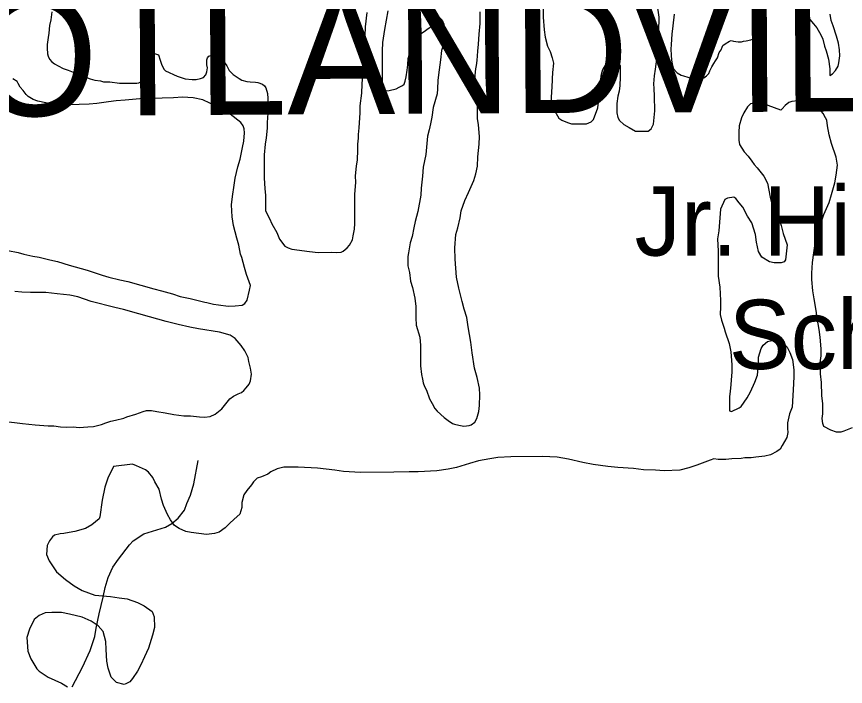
# Model space of a CAD drawing. Extents: x 3313442 to 3351311, y 721974 to 747360.
# Drawn here: x 3330734 to 3331726, y 737982 to 738784 of the extents above; entities that cross this region are included whole.
import ezdxf

# ---------------------------------------------------------------- set-up
doc = ezdxf.new("R2010")
doc.units = 0
for name, color, linetype in [('V-BLDG-IDEN', 7, 'Continuous'), ('V-SITE-VEGE', 7, 'Continuous'), ('V-TOPO-GNAM-IDEN', 7, 'Continuous'), ('V-TOPO-SHOR', 7, 'Continuous')]:
    doc.layers.add(name, color=color, linetype=linetype)

msp = doc.modelspace()

# ---------------------------------------------------------------- linework, layer by layer
at = {"layer": 'V-SITE-VEGE'}
for points in [[(3331364.25, 738793.3), (3331364.33, 738783.3), (3331365.48, 738768.15), (3331366.59, 738759.2), (3331369.43, 738748.54), (3331372.58, 738742.36), (3331375.06, 738734.8), (3331376.49, 738728.26), (3331375.54, 738716.88), (3331375.26, 738709.64), (3331374.66, 738698.61), (3331374.34, 738695.16), (3331373.73, 738685.85), (3331373.77, 738680.34), (3331376.94, 738672.09), (3331379.73, 738667.98), (3331383.22, 738662.49), (3331386.68, 738660.11), (3331393.26, 738657.06), (3331398.09, 738655.72), (3331401.88, 738655.75), (3331406.71, 738655.45), (3331416.36, 738655.53), (3331421.85, 738657.98), (3331424.58, 738660.76), (3331429.64, 738674.59), (3331431.92, 738691.49), (3331432.19, 738700.45), (3331432.83, 738706.32), (3331434.14, 738714.94), (3331435.82, 738720.47), (3331441.59, 738731.2), (3331443.64, 738733.28), (3331446.05, 738733.65), (3331448.12, 738733.66), (3331450.9, 738731.62), (3331453.33, 738729.22), (3331456.46, 738725.46), (3331456.57, 738711.33), (3331455.96, 738701.68), (3331455.33, 738694.78), (3331453.65, 738688.56), (3331452.34, 738679.94), (3331452.43, 738668.91), (3331453.52, 738663.06), (3331455.61, 738659.63), (3331460.82, 738654.85), (3331467.39, 738651.11), (3331474.67, 738646.69), (3331490.17, 738646.82), (3331493.6, 738649.6), (3331494.95, 738652.02), (3331496.31, 738655.14), (3331497.9, 738671.34), (3331497.76, 738688.92), (3331497, 738697.87), (3331496.96, 738703.39), (3331497.56, 738713.04), (3331498.88, 738720.97), (3331502.14, 738744.44), (3331503.09, 738755.12), (3331502.95, 738772.01), (3331503.25, 738777.53), (3331503.2, 738783.39), (3331500.66, 738799.9)], [(3330776.03, 738789.6), (3330774.73, 738780.28), (3330773.06, 738773.38), (3330772.45, 738764.07), (3330771.46, 738758.89), (3330770.49, 738750.61), (3330770.53, 738746.14), (3330770.93, 738739.59), (3330771.64, 738736.5), (3330773.39, 738733.06), (3330776.17, 738729.98), (3330779.29, 738727.25), (3330783.45, 738724.87), (3330789.67, 738721.82), (3330795.55, 738719.8), (3330807.65, 738715.07), (3330821.82, 738709.33), (3330827.35, 738708), (3330834.25, 738707.02), (3330838.05, 738706.01), (3330845.29, 738705.73), (3330857.01, 738704.44), (3330860.46, 738704.47), (3330868.39, 738704.19), (3330877.69, 738704.26), (3330880.1, 738704.63), (3330882.84, 738706.37), (3330884.55, 738708.8), (3330884.53, 738711.21), (3330884.84, 738715), (3330884.82, 738718.11), (3330886.82, 738725.7), (3330888.15, 738731.57), (3330888.46, 738736.4), (3330890.5, 738739.52), (3330895.67, 738739.9), (3330900.15, 738739.59), (3330903.61, 738738.24), (3330905.73, 738731.71), (3330907.15, 738726.9), (3330909.95, 738721.06), (3330912.03, 738719.01), (3330926.21, 738712.58), (3330935.54, 738709.55), (3330944.17, 738708.59), (3330948.65, 738708.63), (3330954.15, 738709.7), (3330957.58, 738711.11), (3330960.31, 738714.23), (3330961.67, 738717.69), (3330962.32, 738722.52), (3330961.6, 738726.31), (3330961.55, 738732.16), (3330962.56, 738734.58), (3330963.93, 738736.66), (3330969.77, 738738.78), (3330975.64, 738737.79), (3330980.15, 738733.35), (3330982.6, 738728.89), (3330985.73, 738725.12), (3330988.53, 738719.63), (3330990.62, 738717.24), (3330993.05, 738714.84), (3331000.33, 738709.73), (3331003.44, 738708.03), (3331009.66, 738706.36), (3331013.46, 738705.7), (3331020, 738705.41), (3331022.76, 738705.09), (3331028.29, 738703.06), (3331030.72, 738701.01), (3331032.12, 738698.61), (3331034.24, 738691.74), (3331034.63, 738685.88), (3331034.72, 738675.89), (3331034.43, 738668.31)], [(3331034.43, 738668.31), (3331033.83, 738657.28), (3331033.89, 738650.38), (3331032.6, 738638.66), (3331031.63, 738631.07), (3331030.35, 738618.31), (3331030.42, 738610.04), (3331030.19, 738595.91), (3331030.23, 738591.08), (3331031.02, 738577.65), (3331031.77, 738570.07), (3331031.92, 738551.46), (3331036.48, 738542.2), (3331039.28, 738536.02), (3331045.23, 738525.38), (3331048.74, 738517.48), (3331055.01, 738509.26), (3331059.16, 738506.89), (3331063.31, 738505.54), (3331084.35, 738502.61), (3331094.7, 738501.66), (3331110.55, 738501.79), (3331117.1, 738501.49), (3331122.27, 738501.88), (3331125.01, 738502.94), (3331129.8, 738507.11), (3331132.54, 738510.23), (3331135.93, 738516.81), (3331136.93, 738521.3), (3331138.24, 738529.58), (3331138.87, 738536.13), (3331138.66, 738562.66), (3331138.94, 738571.28), (3331139.86, 738585.42), (3331139.79, 738593.34), (3331140.73, 738605.07), (3331142.06, 738612.31), (3331142.31, 738624.03), (3331142.25, 738631.27), (3331143.22, 738638.51), (3331143.19, 738642.99), (3331144.15, 738650.93), (3331145.04, 738668.85), (3331145.32, 738677.12), (3331147.27, 738692.3), (3331147.52, 738702.99), (3331148.17, 738709.2), (3331149.47, 738718.51), (3331149.76, 738725.06), (3331150.72, 738735.06), (3331150.66, 738742.64), (3331151.26, 738753.33), (3331151.2, 738760.91), (3331151.46, 738771.6), (3331153.73, 738788.84)], [(3331178.18, 738791.11), (3331174.22, 738768.68), (3331171.94, 738752.81), (3331171.67, 738743.16), (3331171.44, 738728.68), (3331171.68, 738699.39), (3331172.4, 738695.26), (3331179.98, 738695.32), (3331188.23, 738697.46), (3331192.01, 738699.56), (3331195.79, 738701.31), (3331197.84, 738703.05), (3331199.19, 738706.85), (3331200.18, 738712.03), (3331201.49, 738719.96), (3331202.13, 738726.17), (3331202.76, 738733.76), (3331203.76, 738737.9), (3331205.79, 738742.4), (3331207.14, 738746.2), (3331209.5, 738753.8), (3331210.85, 738756.22), (3331214.95, 738761.08), (3331217.34, 738763.51), (3331221.8, 738766.3), (3331224.88, 738768.4), (3331230.02, 738772.23), (3331233.79, 738775.36), (3331238.57, 738780.57), (3331240.62, 738782.65), (3331243.4, 738779.92), (3331245.51, 738774.77), (3331245.88, 738770.98)], [(3331288.92, 738775.8), (3331288.81, 738789.59)], [(3331521.1, 738786.97), (3331519.48, 738772.83), (3331518.53, 738762.83), (3331517.6, 738750.76), (3331517.3, 738744.9), (3331517.35, 738737.67), (3331518.09, 738731.81), (3331519.18, 738725.62), (3331520.24, 738721.49), (3331524.76, 738716.7), (3331529.61, 738713.99), (3331532.37, 738712.97), (3331537.55, 738711.64), (3331539.97, 738710.62), (3331544.8, 738709.97), (3331551.7, 738709.34), (3331554.11, 738709.36), (3331556.86, 738710.76), (3331559.94, 738713.2), (3331562.67, 738715.97), (3331564.03, 738719.09), (3331566.4, 738723.93), (3331568.44, 738727.74), (3331570.48, 738731.2), (3331572.86, 738734.67), (3331575.22, 738740.89), (3331577.26, 738744.35), (3331578.62, 738747.46), (3331579.29, 738749.54), (3331582.38, 738751.28), (3331587.52, 738754.42), (3331589.58, 738755.48), (3331592.35, 738754.46), (3331597.86, 738753.82), (3331601.66, 738753.85), (3331604.06, 738754.56), (3331607.5, 738754.93), (3331613.01, 738756.01), (3331615.07, 738757.06), (3331617.46, 738758.8), (3331618.14, 738760.88), (3331619.14, 738765.36), (3331620.48, 738769.16), (3331622.5, 738776.07), (3331623.49, 738780.91), (3331623.43, 738788.83)], [(3331676.48, 738790.29), (3331683.46, 738780.35), (3331687.98, 738775.22), (3331691.81, 738770.43), (3331696.7, 738762.19), (3331699.15, 738757.05), (3331701.29, 738748.79), (3331703.06, 738742.95), (3331705.89, 738732.98), (3331707.36, 738721.62), (3331707.43, 738713.35), (3331710.86, 738715.44), (3331714.27, 738719.61), (3331717.67, 738724.8), (3331718.33, 738728.6), (3331719.3, 738737.22), (3331719.24, 738744.11), (3331717.8, 738752.37), (3331715.32, 738760.62), (3331711.43, 738772.99), (3331709.31, 738779.18), (3331707.87, 738787.1)], [(3331245.88, 738770.98), (3331245.92, 738766.5), (3331245.62, 738760.29), (3331244.67, 738749.95), (3331242.66, 738743.38), (3331241.37, 738732.34), (3331239.1, 738714.41), (3331238.12, 738707.51), (3331237.86, 738697.51), (3331237.21, 738691.65), (3331232.52, 738675.07), (3331230.89, 738663.68), (3331229.24, 738655.75), (3331227.91, 738648.5), (3331225.91, 738640.9), (3331224.64, 738627.45), (3331223.67, 738618.83), (3331220.69, 738603.64), (3331219.75, 738592.95), (3331218.14, 738578.46), (3331217.86, 738570.19), (3331214.23, 738550.52), (3331210.88, 738538.78), (3331209.56, 738530.84), (3331207.58, 738520.83), (3331205.23, 738512.89), (3331202.91, 738501.15), (3331202.26, 738496.67), (3331202.34, 738485.64), (3331204.13, 738477.73), (3331205.59, 738467.06), (3331207.72, 738459.49), (3331210.58, 738446.76), (3331211.7, 738436.78), (3331211.81, 738423.34), (3331212.22, 738414.38), (3331216.81, 738400.29), (3331217.24, 738390.3), (3331217.44, 738365.84), (3331218.55, 738355.51), (3331219.63, 738349.66), (3331220.7, 738345.53), (3331222.12, 738341.06), (3331224.56, 738336.6), (3331228.09, 738326.29), (3331231.58, 738320.46), (3331234.39, 738314.63), (3331237.51, 738311.55), (3331245.84, 738304.04), (3331250.7, 738300.28), (3331255.55, 738296.88), (3331257.97, 738295.86), (3331263.5, 738294.53), (3331269.36, 738293.54), (3331275.56, 738294.28), (3331277.97, 738294.99), (3331282.42, 738298.47), (3331284.8, 738302.63), (3331287.14, 738310.92), (3331288.12, 738318.16), (3331288.36, 738330.91), (3331287.95, 738339.18), (3331285.09, 738351.91), (3331282.25, 738362.91), (3331279.34, 738381.5), (3331277.86, 738394.23), (3331274.61, 738412.47), (3331272.79, 738423.83), (3331269.62, 738433.45), (3331267.48, 738442.74), (3331263.21, 738458.9), (3331260.69, 738471.98), (3331258.8, 738493.33), (3331258.34, 738507.11), (3331259.59, 738522.97), (3331261.94, 738530.92), (3331264.95, 738543), (3331266.26, 738551.29), (3331270.64, 738563.72), (3331274.7, 738573.41), (3331281.13, 738587.59), (3331283.82, 738595.53), (3331285.47, 738604.85), (3331286.07, 738616.23), (3331287.67, 738631.06), (3331287.94, 738640.36), (3331286.79, 738654.48), (3331285.7, 738662.06), (3331285.61, 738673.43), (3331285.2, 738681.35), (3331284.08, 738692.37), (3331283.68, 738699.26), (3331282.91, 738708.56), (3331282.87, 738713.72), (3331283.84, 738721.31), (3331284.5, 738725.45), (3331285.14, 738731.32), (3331286.08, 738742.7), (3331287.05, 738750.97), (3331287.64, 738763.04), (3331288.92, 738775.8)], [(3330723.2, 738503.84), (3330735.62, 738501.53), (3330742.53, 738499.51), (3330753.23, 738497.19), (3330760.82, 738495.87), (3330773.6, 738492.87), (3330782.92, 738490.54), (3330796.74, 738486.17), (3330818.5, 738480.14), (3330822.99, 738478.8), (3330836.46, 738474.43), (3330844.41, 738472.08), (3330857.53, 738468.74), (3330866.85, 738466.74), (3330897.94, 738458.03), (3330907.26, 738455.7), (3330920.38, 738452.01), (3330929.71, 738448.98), (3330941.45, 738446.32), (3330959.06, 738441.98), (3330961.48, 738441.66), (3330969.76, 738439.66), (3330975.63, 738438.67), (3330987.01, 738437.39), (3330995.62, 738437.45), (3331003.89, 738438.56), (3331006.97, 738440.3), (3331009.7, 738444.46), (3331012.7, 738456.2), (3331013.69, 738462.07), (3331009.1, 738475.13), (3331006.62, 738483.72), (3331003.43, 738495.41), (3331002.02, 738499.53), (3330999.86, 738510.2), (3330997.38, 738518.8), (3330993.47, 738533.93), (3330992.01, 738544.25), (3330991.2, 738558.72), (3330992.16, 738568.38), (3330994.12, 738582.18), (3330995.43, 738590.46), (3330998.76, 738604.27), (3331001.45, 738613.25), (3331004.44, 738627.06), (3331005.75, 738634.99), (3331006.71, 738644.65), (3331006.33, 738649.47), (3331005.26, 738653.26), (3331002.12, 738657.36), (3330989.64, 738667.26), (3330977.87, 738673.71), (3330965.07, 738680.5), (3330956.77, 738684.22), (3330945.38, 738686.55), (3330932.62, 738687.48), (3330921.6, 738686.7), (3330881.29, 738685.69), (3330863.73, 738683.82), (3330853.05, 738683.05), (3330843.75, 738681.94), (3330829.99, 738679.76), (3330820.69, 738679.34), (3330808.63, 738678.55), (3330787.96, 738678.39), (3330782.78, 738679.04), (3330774.51, 738679.66), (3330768.64, 738680.65), (3330759.32, 738682.64), (3330753.79, 738684.66), (3330749.64, 738687.04), (3330747.56, 738688.4), (3330745.47, 738690.8), (3330741.64, 738695.59), (3330738.17, 738699.35), (3330735.72, 738703.81), (3330734.67, 738706.22), (3330729.47, 738709.62)], [(3331690.41, 738515.41), (3331691.75, 738520.24), (3331700.5, 738546.85), (3331706.58, 738561.37), (3331709.61, 738571.04), (3331713.63, 738584.86), (3331715.28, 738594.18), (3331716.56, 738606.25), (3331715.11, 738615.54), (3331709.46, 738632.04), (3331706.62, 738642.35), (3331704.81, 738653.36), (3331704.07, 738659.91), (3331700.92, 738665.74), (3331699.87, 738667.45), (3331697.09, 738670.88), (3331690.16, 738675.3), (3331681.85, 738679.71), (3331673.91, 738682.41), (3331668.73, 738683.06), (3331661.85, 738682.31), (3331658.41, 738681.25), (3331653.96, 738677.42), (3331650.54, 738673.61), (3331648.83, 738671.87), (3331633.63, 738677.61), (3331628.09, 738679.97), (3331625.68, 738680.64), (3331621.88, 738680.96), (3331618.09, 738680.93), (3331612.59, 738679.5), (3331608.83, 738676.03), (3331604.75, 738668.76), (3331601.7, 738662.87), (3331599.02, 738653.2), (3331598.39, 738645.62), (3331598.47, 738635.97), (3331599.2, 738630.81), (3331605.13, 738621.89), (3331609.65, 738616.76), (3331614.17, 738610.94), (3331616.96, 738606.83), (3331620.44, 738603.06), (3331628.45, 738592.79), (3331633, 738584.56), (3331635.89, 738567.69), (3331638.38, 738558.41), (3331640.49, 738552.91), (3331646.43, 738541.93), (3331649.26, 738533.68), (3331651.74, 738524.4), (3331656.33, 738510.65), (3331654.41, 738492.72), (3331652.71, 738490.29), (3331649.27, 738489.23), (3331641, 738489.17), (3331635.13, 738490.15), (3331626.13, 738495.94), (3331622.28, 738502.8), (3331619.78, 738513.8), (3331618.33, 738523.1), (3331614.08, 738536.85), (3331608.85, 738545.08), (3331603.25, 738555.71), (3331599.07, 738560.85), (3331594.89, 738566.33), (3331592.47, 738567.69), (3331584.89, 738566.59), (3331581.81, 738564.85), (3331576.73, 738553.43), (3331575.78, 738543.09), (3331574.52, 738527.57), (3331572.88, 738517.91), (3331573.69, 738503.1), (3331573.93, 738473.12), (3331575.76, 738460.04), (3331576.58, 738443.85), (3331576.64, 738436.61), (3331576.02, 738427.3), (3331577.8, 738420.42), (3331580.98, 738410.8), (3331582.04, 738406.67), (3331586.98, 738392.58), (3331589.13, 738382.61), (3331590.29, 738367.11), (3331590.36, 738358.15), (3331589.4, 738348.84), (3331589.1, 738342.98), (3331588.13, 738335.39), (3331587.5, 738328.49), (3331587.25, 738316.78), (3331587.29, 738311.95), (3331589.71, 738310.94), (3331598.97, 738315.49), (3331601.37, 738317.23), (3331608.53, 738327.28), (3331612.61, 738334.55), (3331617.68, 738346.31), (3331620.72, 738354.6), (3331621.99, 738367.71), (3331622.27, 738375.98)], [(3331734.25, 738291.42), (3331724.29, 738287.55), (3331720.51, 738286.49), (3331715.34, 738286.45), (3331708.77, 738288.81), (3331700.47, 738293.22), (3331699.06, 738296.65), (3331698.33, 738302.5), (3331698.97, 738308.37), (3331699.21, 738320.43), (3331698.1, 738330.42), (3331697.63, 738345.92), (3331696.51, 738356.25), (3331696.07, 738369.34), (3331697.03, 738377.62), (3331696.96, 738386.23), (3331695.82, 738400.01), (3331694.71, 738409.3), (3331692.19, 738422.72), (3331691.08, 738432.02), (3331688.9, 738446.13), (3331687.1, 738455.76), (3331685.96, 738469.2), (3331685.9, 738476.78), (3331686.83, 738489.53), (3331690.41, 738515.41)], [(3330718.29, 738299.45), (3330740.71, 738296.87), (3330755.89, 738295.27), (3330771.75, 738294.02), (3330778.3, 738293.73), (3330786.58, 738292.76), (3330793.13, 738292.47), (3330801.74, 738292.54), (3330808.64, 738291.91), (3330818.97, 738292.68), (3330825.86, 738293.08), (3330835.49, 738295.57), (3330840.64, 738297.68), (3330846.49, 738299.45), (3330852.33, 738300.53), (3330862.31, 738303.02), (3330865.74, 738304.77), (3330876.74, 738307.96), (3330885.33, 738311.13), (3330889.46, 738312.2), (3330895.32, 738312.24), (3330901.87, 738311.26), (3330911.54, 738309.28), (3330921.89, 738307.29), (3330933.96, 738306.01), (3330941.89, 738305.73), (3330952.92, 738304.78), (3330958.79, 738304.48), (3330965.67, 738305.23), (3330971.51, 738307.69), (3330979.73, 738314.3), (3330984.5, 738320.2), (3330989.28, 738326.44), (3330993.39, 738329.58), (3330999.23, 738332.38), (3331003, 738333.79), (3331005.74, 738336.22), (3331008.82, 738339.35), (3331012.23, 738343.85), (3331013.92, 738347.66), (3331014.89, 738355.94), (3331013.8, 738362.82), (3331012.01, 738371.08), (3331010.94, 738375.55), (3331007.08, 738383.79), (3331002.55, 738389.96), (3330995.59, 738398.51), (3330989.36, 738402.6), (3330976.58, 738405.94), (3330951.74, 738409.88), (3330941.38, 738412.21), (3330927.23, 738415.19), (3330913.07, 738418.87), (3330893.04, 738424.57), (3330880.26, 738427.91), (3330861.95, 738433.28), (3330851.25, 738435.6), (3330823.28, 738442.96), (3330807.04, 738448.34), (3330797.37, 738450.33), (3330782.2, 738451.93), (3330768.74, 738453.55), (3330750.48, 738453.75), (3330740.14, 738454.01), (3330731.52, 738454.97)], [(3331622.27, 738375.98), (3331625.29, 738386.34), (3331627.66, 738390.5), (3331632.8, 738395.02), (3331637.96, 738396.1), (3331645.54, 738396.5), (3331651.42, 738393.79), (3331656.29, 738387.97), (3331659.44, 738381.8), (3331662.95, 738373.21), (3331664.43, 738361.16), (3331664.49, 738353.58), (3331663.87, 738344.27), (3331663.3, 738330.14), (3331662.38, 738316.34), (3331659.34, 738308.39), (3331656.67, 738297.34), (3331656.72, 738290.8), (3331657.11, 738285.98), (3331656.12, 738280.11), (3331650.34, 738270.41), (3331647.96, 738265.92), (3331644.19, 738263.13), (3331636.3, 738259.28), (3331629.77, 738257.5), (3331619.09, 738256.38), (3331613.24, 738255.64), (3331605.66, 738255.58), (3331601.53, 738254.86), (3331590.16, 738254.42), (3331582.93, 738253.68), (3331573.63, 738253.6), (3331568.8, 738254.25), (3331564.33, 738252.84), (3331548.18, 738246.85), (3331538.56, 738243.67), (3331527.9, 738240.83), (3331509.29, 738239.99), (3331498.61, 738240.94), (3331484.47, 738241.17), (3331472.4, 738242.8), (3331453.78, 738244.02), (3331441.71, 738245.3), (3331424.12, 738247.58), (3331411.69, 738249.89), (3331394.43, 738253.89), (3331380.97, 738256.19), (3331363.39, 738257.08), (3331325.48, 738256.77), (3331309.98, 738255.96), (3331300.35, 738254.51), (3331286.93, 738251.99), (3331276.27, 738248.8), (3331260.46, 738243.85), (3331250.48, 738242.04), (3331237.06, 738240.21), (3331214.67, 738239), (3331203.98, 738238.91), (3331185.38, 738238.42), (3331145.75, 738238.1), (3331125.06, 738239.31), (3331114.71, 738240.95), (3331094.02, 738243.2), (3331070.92, 738244.39), (3331053.69, 738244.6), (3331045.78, 738242.47), (3331038.23, 738238.96), (3331034.8, 738236.18), (3331026.9, 738233.01), (3331021.75, 738231.25), (3331017.31, 738226.73), (3331014.92, 738223.27), (3331009.46, 738216.33), (3331006.06, 738211.13), (3331003.37, 738202.15), (3331003.42, 738196.29), (3331001.08, 738188.01), (3330994.23, 738182.09), (3330988.76, 738176.88), (3330983.63, 738171.67), (3330976.44, 738166.44), (3330970.59, 738165.02), (3330961.29, 738163.91), (3330943.01, 738166.17), (3330936.45, 738167.5), (3330928.5, 738170.88), (3330922.96, 738174.62), (3330918.08, 738181.48), (3330914.58, 738187.65), (3330909.67, 738198.64), (3330907.2, 738206.2), (3330904.69, 738217.9), (3330899.45, 738226.82), (3330897, 738231.97), (3330891.77, 738238.47), (3330887.96, 738241.2), (3330877.24, 738245.94), (3330872.4, 738247.96), (3330850.02, 738245.37), (3330842.9, 738231.19), (3330839.54, 738220.48)], [(3330839.54, 738220.48), (3330836.22, 738204.94), (3330833.62, 738184.94), (3330832.61, 738182.51), (3330823.7, 738175.21), (3330816.5, 738171.01), (3330803.44, 738167.46), (3330796.56, 738166.03), (3330790.36, 738164.94), (3330785.89, 738164.56), (3330779.01, 738163.13), (3330776.61, 738161.04), (3330773.2, 738156.19), (3330770.49, 738150.66), (3330769.54, 738139.96), (3330772.7, 738132.41), (3330781.77, 738119.04), (3330792.18, 738109.82), (3330802.93, 738102.33), (3330812.28, 738096.55), (3330827.48, 738091.15), (3330846.1, 738089.58), (3330856.8, 738087.94), (3330866.12, 738086.64), (3330878.56, 738082.26), (3330886.51, 738078.53), (3330896.22, 738071.37), (3330898.68, 738065.19), (3330898.78, 738052.44), (3330896.45, 738043.12), (3330891.75, 738027.57), (3330887, 738017.2), (3330882.6, 738007.86), (3330878.53, 737999.9), (3330872.74, 737991.24), (3330869.33, 737987.42), (3330864.52, 737984.97), (3330862.46, 737984.26), (3330853.48, 737986.6), (3330846.88, 737993.1), (3330843.35, 738003.75), (3330841.9, 738012.01), (3330841.1, 738026.13), (3330840.68, 738035.43), (3330837.48, 738047.47), (3330831.57, 738054.31), (3330822.91, 738060.1), (3330812.19, 738064.84), (3330797, 738068.51), (3330787.68, 738070.16), (3330775.96, 738070.41), (3330768.04, 738070), (3330760.83, 738066.84), (3330755.01, 738061.97), (3330749.24, 738050.2), (3330745.88, 738040.53), (3330747.39, 738024), (3330750.91, 738014.72), (3330758.23, 738003.07), (3330760.67, 737999.98), (3330771.76, 737992.84), (3330787.67, 737985.73), (3330794.94, 737981.31)]]:
    msp.add_lwpolyline(points, dxfattribs=at)
at = {"layer": 'V-TOPO-SHOR'}
msp.add_lwpolyline([(3330800.49, 737981.36), (3330812.57, 738004.99), (3330821.9, 738024.65), (3330827.31, 738041.51), (3330829.01, 738051.61), (3330832.63, 738068.65), (3330837.41, 738088.67), (3330839.69, 738100.16), (3330843.35, 738112.26), (3330848.99, 738124.76), (3330855.84, 738134.11), (3330868.95, 738151.23), (3330873.46, 738156.21), (3330886.25, 738164.43), (3330912.3, 738172.55), (3330919.78, 738176.76), (3330927.25, 738183.15), (3330934.88, 738192.71), (3330937.78, 738201.04), (3330942.06, 738210.77), (3330945.9, 738224.45), (3330951.22, 738252.58)], dxfattribs=at)

# ---------------------------------------------------------------- texts
at = {"layer": 'V-BLDG-IDEN'}
for s, p in [('Jr. High', (3331473.8, 738497.7)), ('Sch.', (3331586.59, 738361.94))]:
    msp.add_text(s, height=83, dxfattribs=at).set_placement(p)
at = {"layer": 'V-TOPO-GNAM-IDEN'}
msp.add_text('SCOTLANDVILLE', height=144.9997, rotation=0.31789, dxfattribs=at).set_placement((3330411.6, 738663.21))

doc.saveas('drawing.dxf')
